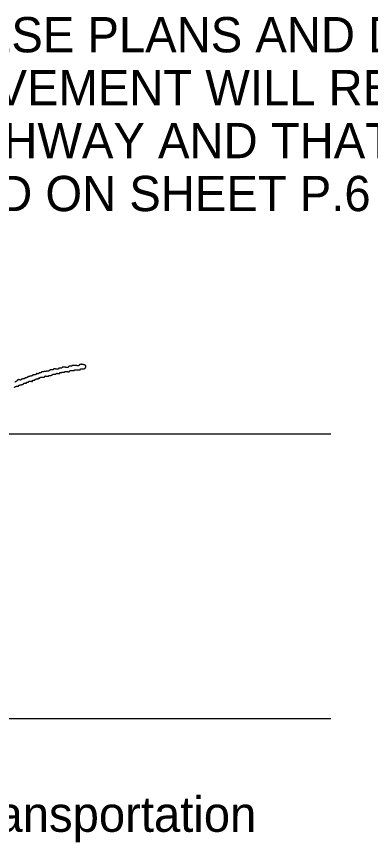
# Model space of a CAD drawing. Extents: x 0 to 34, y 0 to 22.
# Drawn here: x 26.781 to 28.185, y 7.305 to 10.581 of the extents above; entities that cross this region are included whole.
import ezdxf

# ---------------------------------------------------------------- set-up
doc = ezdxf.new("R2010")
doc.units = 0
doc.layers.add('SH_Data', color=7, linetype='Continuous')
doc.layers.add('SH_Text', color=7, linetype='Continuous')

msp = doc.modelspace()

# ---------------------------------------------------------------- linework, layer by layer
at = {"layer": 'SH_Data'}
for p, q in [((24.5279, 8.9262), (28.0279, 8.9262)), ((24.5279, 7.7968), (28.0279, 7.7968))]:
    msp.add_line(p, q, dxfattribs=at)
at = {"layer": 'SH_Text'}
for points in [[(26.9125, 9.177), (26.9125, 9.1758), (26.9049, 9.174), (26.8957, 9.1731)], [(26.9195, 9.1793), (26.9156, 9.1793), (26.9125, 9.1782), (26.9125, 9.177)], [(26.9281, 9.1817), (26.9272, 9.1803), (26.9234, 9.1793), (26.9195, 9.1793)], [(26.939, 9.1826), (26.9336, 9.1834), (26.9289, 9.183), (26.9281, 9.1817)], [(26.9485, 9.1837), (26.9485, 9.1819), (26.9453, 9.1815), (26.939, 9.1826)], [(26.9557, 9.1865), (26.9517, 9.1865), (26.9485, 9.1852), (26.9485, 9.1837)], [(26.9629, 9.1889), (26.9629, 9.1876), (26.9596, 9.1865), (26.9557, 9.1865)], [(26.9749, 9.1898), (26.9672, 9.1908), (26.9629, 9.1905), (26.9629, 9.1889)], [(26.9869, 9.1909), (26.9869, 9.1891), (26.9831, 9.1887), (26.9749, 9.1898)], [(26.9941, 9.1937), (26.9901, 9.1937), (26.9869, 9.1924), (26.9869, 9.1909)], [(26.9917, 9.1741), (26.9917, 9.1757), (26.9957, 9.1769), (27.0013, 9.1769)], [(27.0013, 9.1959), (27.0013, 9.1947), (26.998, 9.1937), (26.9941, 9.1937)], [(27.0147, 9.1967), (27.007, 9.1975), (27.0013, 9.1971), (27.0013, 9.1959)], [(27.0013, 9.1769), (27.0065, 9.1769), (27.0109, 9.1777), (27.0109, 9.1787)], [(27.0109, 9.1787), (27.0109, 9.1796), (27.0163, 9.1801), (27.0229, 9.1796)], [(27.0299, 9.1982), (27.0287, 9.1962), (27.0239, 9.1958), (27.0147, 9.1967)], [(27.0229, 9.1796), (27.0309, 9.1791), (27.0349, 9.1797), (27.0349, 9.1816)], [(27.0565, 9.1939), (27.0565, 9.199), (27.0328, 9.2028), (27.0299, 9.1982)], [(27.0349, 9.1816), (27.0349, 9.1832), (27.0376, 9.1841), (27.0415, 9.1836)], [(27.0415, 9.1836), (27.0489, 9.1828), (27.0565, 9.1879), (27.0565, 9.1939)], [(26.8069, 9.1433), (26.8029, 9.1433), (26.7997, 9.1422), (26.7997, 9.1408)], [(26.8141, 9.1457), (26.8141, 9.1443), (26.8108, 9.1433), (26.8069, 9.1433)], [(26.8187, 9.1481), (26.8162, 9.1481), (26.8141, 9.147), (26.8141, 9.1457)], [(26.8247, 9.1502), (26.824, 9.149), (26.8213, 9.1481), (26.8187, 9.1481)], [(26.8357, 9.1541), (26.8304, 9.1532), (26.8255, 9.1515), (26.8247, 9.1502)], [(26.8453, 9.1579), (26.8453, 9.1567), (26.8409, 9.1549), (26.8357, 9.1541)], [(26.8525, 9.1601), (26.8485, 9.1601), (26.8453, 9.1591), (26.8453, 9.1579)], [(26.8597, 9.1627), (26.8597, 9.1613), (26.8564, 9.1601), (26.8525, 9.1601)], [(26.8549, 9.1409), (26.8549, 9.1422), (26.8581, 9.1433), (26.8621, 9.1433)], [(26.8645, 9.1642), (26.8618, 9.1649), (26.8597, 9.1642), (26.8597, 9.1627)], [(26.8621, 9.1433), (26.866, 9.1433), (26.8693, 9.1444), (26.8693, 9.1458)], [(26.8693, 9.1651), (26.8693, 9.1639), (26.8671, 9.1635), (26.8645, 9.1642)], [(26.8741, 9.1673), (26.8714, 9.1673), (26.8693, 9.1663), (26.8693, 9.1651)], [(26.8693, 9.1458), (26.8693, 9.1472), (26.8703, 9.1477), (26.8717, 9.1469)], [(26.8717, 9.1469), (26.873, 9.146), (26.8741, 9.1465), (26.8741, 9.1479)], [(26.8789, 9.1693), (26.8789, 9.1682), (26.8767, 9.1673), (26.8741, 9.1673)], [(26.8741, 9.1479), (26.8741, 9.1493), (26.8784, 9.1505), (26.8837, 9.1505)], [(26.8957, 9.1731), (26.8864, 9.1722), (26.8789, 9.1705), (26.8789, 9.1693)], [(26.8837, 9.1505), (26.8891, 9.1505), (26.8933, 9.1516), (26.8933, 9.1531)], [(26.8933, 9.1531), (26.8933, 9.1547), (26.8962, 9.1554), (26.9006, 9.1547)], [(26.9006, 9.1547), (26.9046, 9.1541), (26.9084, 9.1546), (26.9091, 9.1557)], [(26.9091, 9.1557), (26.9098, 9.1568), (26.9129, 9.1577), (26.9161, 9.1577)], [(26.9161, 9.1577), (26.9192, 9.1577), (26.9224, 9.1587), (26.9233, 9.1601)], [(26.9233, 9.1601), (26.9241, 9.1614), (26.9279, 9.1625), (26.9318, 9.1625)], [(26.9318, 9.1625), (26.9357, 9.1625), (26.9389, 9.1633), (26.9389, 9.1644)], [(26.9389, 9.1644), (26.9389, 9.1655), (26.9421, 9.1659), (26.9461, 9.1654)], [(26.9461, 9.1654), (26.9504, 9.1647), (26.9533, 9.1654), (26.9533, 9.167)], [(26.9533, 9.167), (26.9533, 9.1685), (26.9574, 9.1697), (26.9629, 9.1697)], [(26.9629, 9.1697), (26.9681, 9.1697), (26.9725, 9.1706), (26.9725, 9.1718)], [(26.9725, 9.1718), (26.9725, 9.173), (26.9768, 9.1734), (26.9821, 9.1727)], [(26.9821, 9.1727), (26.9884, 9.1719), (26.9917, 9.1724), (26.9917, 9.1741)], [(26.7731, 9.1094), (26.7755, 9.1122), (26.7803, 9.1145), (26.7837, 9.1145)], [(26.7831, 9.1363), (26.7807, 9.1335), (26.7769, 9.1313), (26.7748, 9.1313)], [(26.7936, 9.1399), (26.7891, 9.141), (26.7863, 9.1401), (26.7831, 9.1363)], [(26.7837, 9.1145), (26.7872, 9.1145), (26.7901, 9.1154), (26.7901, 9.1166)], [(26.7901, 9.1166), (26.7901, 9.1178), (26.7944, 9.1196), (26.7997, 9.1205)], [(26.7997, 9.1408), (26.7997, 9.1394), (26.7971, 9.139), (26.7936, 9.1399)], [(26.7997, 9.1205), (26.8049, 9.1213), (26.8093, 9.1231), (26.8093, 9.1243)], [(26.8093, 9.1243), (26.8093, 9.1255), (26.812, 9.1265), (26.8153, 9.1265)], [(26.8153, 9.1265), (26.8186, 9.1265), (26.8213, 9.1275), (26.8213, 9.1289)], [(26.8213, 9.1289), (26.8213, 9.1302), (26.8234, 9.1313), (26.8261, 9.1313)], [(26.8261, 9.1313), (26.8287, 9.1313), (26.8309, 9.1323), (26.8309, 9.1336)], [(26.8309, 9.1336), (26.8309, 9.1349), (26.834, 9.1353), (26.8381, 9.1345)], [(26.8381, 9.1345), (26.8426, 9.1336), (26.8453, 9.134), (26.8453, 9.1358)], [(26.8453, 9.1358), (26.8453, 9.1372), (26.8474, 9.1385), (26.8501, 9.1385)], [(26.8501, 9.1385), (26.8527, 9.1385), (26.8549, 9.1395), (26.8549, 9.1409)]]:
    msp.add_open_spline(points, degree=2, dxfattribs=at)

# ---------------------------------------------------------------- texts
for s, p in [('I HEREBY APPROVE THESE PLANS AND DECLARE THAT THE', (24.5035, 10.4391)), ('MAKING OF THIS IMPROVEMENT WILL REQUIRE THE CLOSING ', (24.5035, 10.2291)), ('TO TRAFFIC OF THE HIGHWAY AND THAT DETOURS WILL BE ', (24.5035, 10.0191)), ('PROVIDED AS INDICATED ON SHEET P.6', (24.5035, 9.8091)), ('Director, Department of Transportation', (24.5279, 7.3468))]:
    msp.add_text(s, height=0.14, dxfattribs=at).set_placement(p)

doc.saveas('drawing.dxf')
